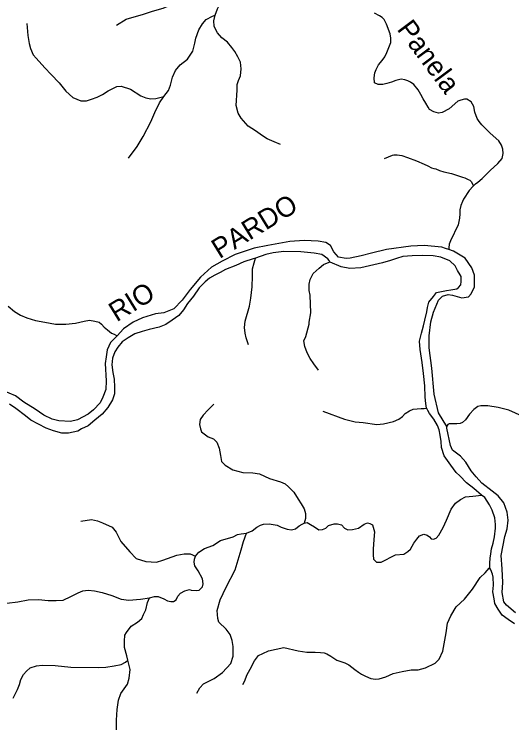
# Model space of a CAD drawing. Extents: x 436.3 to 500.4, y 8231 to 8286.4.
# Drawn here: x 451.75 to 456.78, y 8274.32 to 8281.47 of the extents above; entities that cross this region are included whole.
import ezdxf
from ezdxf.enums import TextEntityAlignment as Align

# ---------------------------------------------------------------- set-up
doc = ezdxf.new("R2010")
doc.units = 0
doc.header["$LTSCALE"] = 0.08
doc.linetypes.add('LONG_DASHED', pattern=[7.5, 6, -1.5])
for name, color, linetype, lineweight in [('2', 7, 'Continuous', 25), ('7', 7, 'Continuous', 25), ('9', 7, 'LONG_DASHED', 25)]:
    doc.layers.add(name, color=color, linetype=linetype, lineweight=lineweight)
doc.layers.add('61', color=7, linetype='Continuous')

msp = doc.modelspace()

# ---------------------------------------------------------------- linework, layer by layer
at = {"layer": '2'}
for points in [[(456.1431, 8279.0995), (456.1124, 8279.1098), (456.0752, 8279.1222), (455.8941, 8279.1388), (455.7603, 8279.1332), (455.5152, 8279.0999), (455.3647, 8279.0611), (455.2589, 8279.0334), (455.1474, 8279.0112), (455.1085, 8279.0068), (455.0304, 8279.0224), (454.9814, 8279.0757), (454.9483, 8279.1393), (454.9025, 8279.1697), (454.8236, 8279.1826), (454.6846, 8279.1901), (454.5396, 8279.1792), (454.3167, 8279.1406), (454.1772, 8279.113), (453.9876, 8279.0465), (453.8538, 8278.98), (453.7478, 8278.9189), (453.6363, 8278.8187), (453.5304, 8278.6964), (453.4509, 8278.5869), (453.3673, 8278.498), (453.2668, 8278.4591), (453.1832, 8278.4482), (453.0494, 8278.4094), (452.9546, 8278.3651), (452.8598, 8278.2984), (452.7944, 8278.2282)], [(456.0416, 8278.5878), (456.0805, 8278.6268), (456.1363, 8278.6435), (456.1808, 8278.6379), (456.2755, 8278.6102), (456.3423, 8278.6214), (456.3702, 8278.6493), (456.4037, 8278.7217), (456.4037, 8278.8385), (456.3761, 8278.9141), (456.3091, 8279.011), (456.1921, 8279.0833), (456.1431, 8279.0995)], [(454.9427, 8278.9736), (454.9344, 8278.986), (454.9229, 8279.0046), (454.8601, 8279.0465), (454.7858, 8279.0618), (454.6508, 8279.0754), (454.4795, 8279.0795), (454.3697, 8279.0658), (454.2954, 8279.0488), (454.1922, 8279.0117)], [(455.9875, 8279.0339), (455.8829, 8279.0377), (455.7726, 8279.0358), (455.6795, 8279.0264), (455.6167, 8279.0093), (455.554, 8278.9865), (455.4759, 8278.9638)], [(455.9204, 8277.4976), (455.9136, 8277.5423), (455.906, 8277.6069), (455.9022, 8277.7211), (455.8888, 8277.8466), (455.8736, 8277.9587), (455.8565, 8278.0896), (455.8489, 8278.1732), (455.8679, 8278.2531), (455.8889, 8278.3272), (455.9022, 8278.3862), (455.9212, 8278.4698), (455.9293, 8278.5128), (455.9426, 8278.566), (455.9901, 8278.623), (456.0205, 8278.6629), (456.0529, 8278.6724), (456.1194, 8278.6858), (456.1632, 8278.6915), (456.2259, 8278.701), (456.2431, 8278.7143), (456.2659, 8278.741), (456.2697, 8278.7771), (456.2678, 8278.8246), (456.2583, 8278.8436), (456.2335, 8278.8853), (456.2081, 8278.9353), (456.1548, 8278.9827), (456.0636, 8279.0207), (455.9875, 8279.0339)], [(454.1922, 8279.0117), (454.1678, 8279.0037), (454.0746, 8278.9731), (453.9947, 8278.9372), (453.8881, 8278.8956), (453.8348, 8278.8672), (453.7796, 8278.8406), (453.7263, 8278.8103), (453.6824, 8278.7731), (453.6234, 8278.7105), (453.5644, 8278.6288), (453.5036, 8278.5548), (453.4636, 8278.4883), (453.416, 8278.4314), (453.3504, 8278.3851), (453.2858, 8278.3414), (453.2191, 8278.3149), (453.1182, 8278.2923), (453.0478, 8278.2715), (452.9735, 8278.2469), (452.905, 8278.2052), (452.846, 8278.1654), (452.8022, 8278.1112), (452.7699, 8278.0657), (452.7471, 8278.0029), (452.7415, 8277.9345), (452.7511, 8277.8564), (452.7645, 8277.7899), (452.7665, 8277.71), (452.7666, 8277.6396), (452.7482, 8277.5793), (452.6989, 8277.5034), (452.6438, 8277.435), (452.5695, 8277.3743), (452.5029, 8277.3174), (452.4344, 8277.289), (452.3963, 8277.2643), (452.303, 8277.2436), (452.2364, 8277.2437), (452.1507, 8277.2667), (452.0763, 8277.2954), (451.9227, 8277.3763), (451.8674, 8277.4182), (451.7701, 8277.4945), (451.7071, 8277.5383)], [(455.4759, 8278.9638), (455.2559, 8278.9149), (455.1436, 8278.9055), (455.0561, 8278.9227), (454.9459, 8278.9704), (454.9427, 8278.9736)], [(455.9957, 8277.6374), (455.9734, 8277.8991), (455.9455, 8278.1053), (455.9455, 8278.2278), (455.9622, 8278.367), (455.9914, 8278.4653), (456.0416, 8278.5878)], [(452.7944, 8278.2282), (452.7768, 8278.2096), (452.7282, 8278.1584), (452.6948, 8278.086), (452.6838, 8278.0135), (452.6726, 8277.9467), (452.6841, 8277.774), (452.6786, 8277.6848), (452.6508, 8277.6069), (452.6229, 8277.5513), (452.5561, 8277.479), (452.5003, 8277.4345), (452.3944, 8277.379), (452.3219, 8277.3624), (452.2047, 8277.3682), (452.1377, 8277.385), (452.0539, 8277.4242), (451.9645, 8277.4856), (451.8528, 8277.5582), (451.769, 8277.6196), (451.6405, 8277.6755)], [(456.123, 8277.3107), (456.0402, 8277.4508), (455.9957, 8277.6374)], [(456.4761, 8276.6191), (456.3979, 8276.6869), (456.3237, 8276.742), (456.2553, 8276.8124), (456.2191, 8276.8486), (456.1632, 8276.9225), (456.0967, 8277.0158), (456.0719, 8277.0995), (456.0662, 8277.1586), (456.0586, 8277.2233), (456.0453, 8277.2784), (456.0301, 8277.3222), (455.992, 8277.3869), (455.9483, 8277.442), (455.9328, 8277.4719), (455.9211, 8277.4933), (455.9204, 8277.4976)], [(456.8177, 8275.4285), (456.7286, 8275.5066), (456.7007, 8275.5401), (456.6839, 8275.6351), (456.6893, 8275.7358), (456.6836, 8275.8755), (456.6747, 8276.0095), (456.7112, 8276.1997), (456.7334, 8276.2779), (456.7446, 8276.3673), (456.7333, 8276.4453), (456.7, 8276.5402), (456.6442, 8276.6127), (456.583, 8276.6573), (456.4771, 8276.7408), (456.4215, 8276.8021), (456.3716, 8276.8633), (456.3156, 8276.9526), (456.2623, 8277.0109), (456.181, 8277.0739), (456.1603, 8277.1208), (456.1258, 8277.296), (456.123, 8277.3107)], [(456.5598, 8275.8854), (456.5598, 8275.9326), (456.5617, 8275.9821), (456.5673, 8276.0241), (456.5749, 8276.0757), (456.592, 8276.1329), (456.6054, 8276.1961), (456.6148, 8276.2856), (456.6146, 8276.3213), (456.6089, 8276.3899), (456.5823, 8276.4661), (456.5556, 8276.5194), (456.5083, 8276.5942), (456.484, 8276.6129), (456.4811, 8276.6147), (456.4761, 8276.6191)], [(456.8075, 8275.3192), (456.7428, 8275.363), (456.6839, 8275.4068), (456.642, 8275.4677), (456.6096, 8275.5231), (456.602, 8275.5727), (456.5905, 8275.6415), (456.5942, 8275.7082), (456.5923, 8275.7895), (456.5864, 8275.8219), (456.5686, 8275.863), (456.5601, 8275.8822), (456.5598, 8275.8854)]]:
    msp.add_lwpolyline(points, dxfattribs=at)
at = {"layer": '7'}
for points in [[(456.3914, 8279.7397), (456.3943, 8279.7418), (456.4146, 8279.7603), (456.4371, 8279.7783), (456.481, 8279.816), (456.5625, 8279.8975), (456.6401, 8279.9674), (456.6827, 8280.0178), (456.6935, 8280.0666), (456.689, 8280.1116), (456.6755, 8280.1521), (456.6486, 8280.1971), (456.5632, 8280.2735), (456.4778, 8280.359), (456.4508, 8280.3905), (456.431, 8280.4217), (456.4078, 8280.4837), (456.3969, 8280.5435), (456.3699, 8280.5886), (456.3249, 8280.6156), (456.3025, 8280.6155), (456.2665, 8280.6065), (456.235, 8280.5975), (456.1481, 8280.5185), (456.0783, 8280.4835), (456.0395, 8280.4757), (455.993, 8280.4875), (455.9504, 8280.5123), (455.9342, 8280.5347), (455.9112, 8280.575), (455.8842, 8280.62), (455.8617, 8280.6651), (455.8347, 8280.7101), (455.7924, 8280.7655), (455.7583, 8280.7867), (455.7321, 8280.8032), (455.7005, 8280.8126), (455.6632, 8280.8193), (455.6098, 8280.8049), (455.5649, 8280.7869), (455.5199, 8280.7734), (455.4794, 8280.7645), (455.4308, 8280.7632), (455.3939, 8280.7826), (455.3894, 8280.8321), (455.3984, 8280.8817), (455.4119, 8280.9177), (455.4344, 8280.9627), (455.4704, 8281.0077), (455.4974, 8281.0437), (455.5199, 8281.0887), (455.5604, 8281.1878), (455.5604, 8281.2328), (455.5514, 8281.2779), (455.5154, 8281.3725), (455.4929, 8281.422), (455.4705, 8281.4401), (455.4435, 8281.4581), (455.394, 8281.4852)], [(456.3914, 8279.7397), (456.3898, 8279.7385), (456.3516, 8279.6927), (456.2931, 8279.6072), (456.2841, 8279.5847), (456.2661, 8279.5442), (456.2571, 8279.4993), (456.2571, 8279.4588), (456.2526, 8279.4138), (456.2391, 8279.3463), (456.162, 8279.1863), (456.1484, 8279.1534), (456.1449, 8279.1147), (456.1431, 8279.0995)]]:
    msp.add_lwpolyline(points, dxfattribs=at)
at = {"layer": '9'}
for p, q in [((455.4938, 8280.019), (455.5747, 8280.0513)), ((452.787, 8278.2296), (452.7944, 8278.2282)), ((456.5518, 8275.8799), (456.5598, 8275.8854))]:
    msp.add_line(p, q, dxfattribs=at)
for points in [[(453.7827, 8281.4656), (453.8084, 8281.5279), (453.8487, 8281.6082), (453.889, 8281.714)], [(452.7874, 8281.3631), (452.8865, 8281.4246), (453.0598, 8281.4738), (453.1526, 8281.5045), (453.2578, 8281.5351), (453.3755, 8281.5843), (453.4572, 8281.61)], [(453.2661, 8280.6426), (453.3137, 8280.7046), (453.332, 8280.7594), (453.3544, 8280.8379), (453.3837, 8280.9073), (453.4313, 8280.962), (453.5045, 8281.0203), (453.5594, 8281.1006), (453.5778, 8281.181), (453.5887, 8281.2321), (453.618, 8281.3161), (453.6547, 8281.3781), (453.6949, 8281.4219), (453.7571, 8281.4546), (453.7827, 8281.4656)], [(454.4455, 8280.1585), (454.3797, 8280.1842), (454.3101, 8280.2172), (454.2626, 8280.2466), (454.1931, 8280.2979), (454.1162, 8280.3456), (454.0467, 8280.4261), (454.0175, 8280.4737), (453.9955, 8280.5541), (454.0064, 8280.7075), (454.0061, 8280.7638), (454.0207, 8280.804), (454.039, 8280.8515), (454.0463, 8280.9245), (454.039, 8280.9903), (454.0134, 8281.0451), (453.9841, 8281.0964), (453.9512, 8281.1366), (453.9072, 8281.1915), (453.8524, 8281.2355), (453.8084, 8281.2868), (453.7865, 8281.3233), (453.7755, 8281.3526), (453.7718, 8281.4074), (453.7827, 8281.4656)], [(451.8831, 8281.38), (451.8905, 8281.2593), (451.9053, 8281.179), (451.92, 8281.1278), (451.9457, 8281.0657), (451.975, 8281.0291), (452.0631, 8280.934), (452.1291, 8280.8645), (452.2097, 8280.7804), (452.2758, 8280.6962), (452.3454, 8280.634), (452.4261, 8280.6011), (452.4847, 8280.601), (452.536, 8280.6156), (452.5909, 8280.6374), (452.6459, 8280.6629), (452.7045, 8280.6994), (452.7923, 8280.7431), (452.8363, 8280.7466), (452.9279, 8280.7173), (453.0341, 8280.6514), (453.0835, 8280.6308), (453.1343, 8280.6209), (453.1856, 8280.6245), (453.2661, 8280.6426)], [(452.9076, 8280.022), (452.9953, 8280.1387), (453.0576, 8280.241), (453.1344, 8280.387), (453.1747, 8280.4819), (453.2222, 8280.5805), (453.2661, 8280.6426)], [(455.5747, 8280.0513), (455.5881, 8280.0536), (455.6217, 8280.0536), (455.6704, 8280.0465), (455.7284, 8280.029), (455.8176, 8279.9942), (455.8953, 8279.9604), (455.932, 8279.9434), (455.9704, 8279.9248), (455.9924, 8279.9161), (456.0122, 8279.9118), (456.0517, 8279.8976), (456.0947, 8279.8845), (456.1702, 8279.8649), (456.233, 8279.8464), (456.2818, 8279.83), (456.3073, 8279.8235), (456.3403, 8279.8063), (456.3577, 8279.7982), (456.375, 8279.7819), (456.3878, 8279.753), (456.3914, 8279.7397)], [(454.1194, 8278.1362), (454.098, 8278.2056), (454.0874, 8278.2536), (454.0819, 8278.3123), (454.0873, 8278.3764), (454.1299, 8278.5256), (454.1459, 8278.6056), (454.1565, 8278.723), (454.1618, 8278.8297), (454.1617, 8278.9044), (454.1777, 8278.963), (454.1922, 8279.0117)], [(454.8294, 8277.8789), (454.7814, 8277.943), (454.744, 8277.9965), (454.712, 8278.0553), (454.6906, 8278.1193), (454.6799, 8278.178), (454.7013, 8278.2206), (454.7332, 8278.3433), (454.7332, 8278.3646), (454.7492, 8278.4606), (454.7438, 8278.6366), (454.7331, 8278.6847), (454.7331, 8278.7487), (454.7438, 8278.7967), (454.7758, 8278.8553), (454.8345, 8278.9086), (454.8772, 8278.9459), (454.9347, 8278.9697), (454.9427, 8278.9736)], [(451.6924, 8278.5264), (451.7581, 8278.4734), (451.8175, 8278.4359), (451.8831, 8278.4078), (451.9707, 8278.3828), (452.0643, 8278.364), (452.1723, 8278.3435), (452.2753, 8278.3434), (452.3721, 8278.3556), (452.4626, 8278.3742), (452.5157, 8278.3835), (452.5687, 8278.374), (452.6125, 8278.3646), (452.6375, 8278.3459), (452.6625, 8278.3146), (452.6969, 8278.2865), (452.7375, 8278.2553), (452.7625, 8278.2428), (452.787, 8278.2296)], [(453.7714, 8277.5381), (453.7144, 8277.4811), (453.6626, 8277.4242), (453.6316, 8277.3828), (453.6264, 8277.331), (453.6368, 8277.2894), (453.6472, 8277.2584), (453.6731, 8277.2375), (453.7146, 8277.2064), (453.7665, 8277.1854), (453.8028, 8277.1543), (453.8236, 8277.092), (453.8392, 8277.0194), (453.8497, 8276.9571), (453.886, 8276.9207), (453.9638, 8276.8739), (454.0623, 8276.8478), (454.1659, 8276.8424), (454.2333, 8276.8318), (454.3318, 8276.785), (454.4459, 8276.7536), (454.4924, 8276.7328), (454.5236, 8276.7016), (454.5806, 8276.6496), (454.6221, 8276.5769), (454.6532, 8276.5302), (454.684, 8276.4815), (454.6964, 8276.432), (454.6952, 8276.3836), (454.6821, 8276.3342)], [(456.9774, 8277.3732), (456.7517, 8277.4769), (456.6417, 8277.5034), (456.5392, 8277.5187), (456.4679, 8277.5186), (456.4382, 8277.5127), (456.3966, 8277.4829), (456.3521, 8277.4352), (456.3134, 8277.3787), (456.2838, 8277.3519), (456.26, 8277.3429), (456.2244, 8277.34), (456.1917, 8277.34), (456.165, 8277.34), (456.1482, 8277.338), (456.1359, 8277.33), (456.1248, 8277.3157), (456.123, 8277.3107)], [(454.8722, 8277.4652), (455.091, 8277.3849), (455.1977, 8277.3582), (455.2777, 8277.3528), (455.4164, 8277.3314), (455.4858, 8277.3367), (455.5871, 8277.3634), (455.6404, 8277.3848), (455.6777, 8277.4115), (455.7044, 8277.4435), (455.747, 8277.4702), (455.7844, 8277.4863), (455.8644, 8277.4916), (455.897, 8277.4945), (455.9204, 8277.4976)], [(454.6821, 8276.3342), (454.7147, 8276.3423), (454.7473, 8276.3219), (454.788, 8276.2973), (454.8328, 8276.2686), (454.8694, 8276.2727), (454.9019, 8276.2849), (454.9305, 8276.3134), (454.9874, 8276.3297), (455.02, 8276.3297), (455.0607, 8276.3174), (455.0912, 8276.2848), (455.1238, 8276.2685), (455.1726, 8276.2724), (455.2337, 8276.2847), (455.2907, 8276.3255), (455.3232, 8276.3377), (455.3476, 8276.3336), (455.3721, 8276.3173), (455.3925, 8276.2479), (455.3884, 8276.1704), (455.3803, 8276.0724), (455.3804, 8276.0152), (455.3845, 8275.9703), (455.413, 8275.9417), (455.4619, 8275.9416), (455.6043, 8276.0152), (455.6897, 8276.0233), (455.7303, 8276.0479), (455.7588, 8276.0724), (455.7913, 8276.1337), (455.8198, 8276.1745), (455.8483, 8276.2071), (455.893, 8276.2235), (455.9255, 8276.2154), (455.95, 8276.199), (455.9663, 8276.1786), (455.9907, 8276.1746), (456.0151, 8276.1827), (456.0435, 8276.2155), (456.0882, 8276.293), (456.1207, 8276.3665), (456.1695, 8276.4767), (456.2113, 8276.5383), (456.2641, 8276.5751), (456.3129, 8276.5996), (456.3862, 8276.6079), (456.4761, 8276.6191)], [(452.4262, 8276.3545), (452.5366, 8276.3726), (452.5964, 8276.3586), (452.6471, 8276.34), (452.7437, 8276.2938), (452.7852, 8276.243), (452.8312, 8276.1508), (452.9233, 8276.0446), (452.9878, 8275.9799), (453.0844, 8275.9474), (453.1902, 8275.9425), (453.2545, 8275.9608), (453.3971, 8276.011), (453.4706, 8276.0247), (453.5304, 8276.0245), (453.5869, 8276.0017)], [(454.1023, 8276.2336), (454.157, 8276.2575), (454.2058, 8276.2942), (454.2423, 8276.3144), (454.2709, 8276.3266), (454.331, 8276.3287), (454.4093, 8276.3141), (454.4501, 8276.2937), (454.5112, 8276.2732), (454.5559, 8276.269), (454.5967, 8276.2772), (454.6333, 8276.3097), (454.6618, 8276.326), (454.6821, 8276.3342)], [(453.5869, 8276.0017), (453.6194, 8276.0424), (453.6765, 8276.079), (453.762, 8276.1114), (453.8393, 8276.1602), (453.9655, 8276.1967), (454.0104, 8276.2211), (454.0484, 8276.2292), (454.1023, 8276.2336)], [(453.5997, 8274.6175), (453.6299, 8274.6719), (453.6661, 8274.7142), (453.7746, 8274.7684), (453.859, 8274.8286), (453.9434, 8274.9193), (453.9675, 8274.9918), (453.9674, 8275.0886), (453.9554, 8275.1492), (453.9372, 8275.2098), (453.8949, 8275.2643), (453.8225, 8275.3372), (453.8104, 8275.3735), (453.8044, 8275.4522), (453.8345, 8275.561), (453.8947, 8275.6879), (453.9861, 8275.8657), (454.0463, 8276.0651), (454.0703, 8276.1496), (454.1023, 8276.2336)], [(453.1196, 8275.5821), (453.1701, 8275.5954), (453.2078, 8275.5952), (453.2644, 8275.5714), (453.3021, 8275.5524), (453.335, 8275.5429), (453.3633, 8275.5428), (453.3916, 8275.5616), (453.4056, 8275.5994), (453.4339, 8275.6276), (453.4763, 8275.651), (453.5234, 8275.6652), (453.5422, 8275.6603), (453.594, 8275.6554), (453.6222, 8275.6601), (453.6552, 8275.6931), (453.6646, 8275.7214), (453.6551, 8275.7733), (453.6127, 8275.8537), (453.5797, 8275.9057), (453.5706, 8275.9405), (453.5747, 8275.9731), (453.5869, 8276.0017)], [(454.0628, 8274.7051), (454.0842, 8274.7425), (454.1055, 8274.8014), (454.1375, 8274.8603), (454.1801, 8274.9459), (454.2227, 8274.9994), (454.2655, 8275.0207), (454.3241, 8275.0474), (454.4789, 8275.0793), (454.623, 8275.0469), (454.7088, 8275.0313), (454.7941, 8275.0312), (454.8475, 8275.0311), (454.8849, 8275.0258), (454.9115, 8275.015), (454.9542, 8274.9935), (455.013, 8274.9506), (455.093, 8274.9236), (455.1333, 8274.9044), (455.1944, 8274.8592), (455.2318, 8274.8325), (455.2639, 8274.8109), (455.3014, 8274.7901), (455.3557, 8274.7678), (455.4027, 8274.759), (455.4399, 8274.7626), (455.5092, 8274.7841), (455.5839, 8274.8162), (455.6745, 8274.8376), (455.7651, 8274.8537), (455.8345, 8274.8537), (455.9091, 8274.8751), (456.005, 8274.9234), (456.0478, 8274.9609), (456.0851, 8275.0413), (456.1168, 8275.2289), (456.1327, 8275.3254), (456.1646, 8275.4004), (456.2179, 8275.4916), (456.3031, 8275.5666), (456.3829, 8275.6685), (456.4628, 8275.7863), (456.5108, 8275.8346), (456.5518, 8275.8799)], [(451.6799, 8275.5262), (451.792, 8275.5414), (451.8963, 8275.5605), (452.0007, 8275.564), (452.0973, 8275.556), (452.1798, 8275.5552), (452.2493, 8275.5588), (452.3265, 8275.5935), (452.3999, 8275.6319), (452.4462, 8275.6511), (452.5003, 8275.6586), (452.566, 8275.6507), (452.6432, 8275.635), (452.7415, 8275.6039), (452.8342, 8275.5688), (452.9115, 8275.5569), (453.0311, 8275.5682), (453.1196, 8275.5821)], [(452.9031, 8274.9515), (452.8925, 8274.9964), (452.8689, 8275.0815), (452.8688, 8275.1429), (452.8735, 8275.2043), (452.8876, 8275.2326), (452.9348, 8275.2939), (453.0007, 8275.3361), (453.043, 8275.3738), (453.0619, 8275.4115), (453.0854, 8275.4587), (453.0996, 8275.5342), (453.1196, 8275.5821)], [(451.7425, 8274.5669), (451.7657, 8274.6093), (451.7889, 8274.6557), (451.8082, 8274.706), (451.8198, 8274.7563), (451.8469, 8274.8065), (451.8778, 8274.8413), (451.9164, 8274.876), (451.9783, 8274.8952), (452.0362, 8274.9027), (452.1676, 8274.8983), (452.326, 8274.8824), (452.6096, 8274.8789), (452.6791, 8274.8825), (452.7641, 8274.8938), (452.8336, 8274.9091), (452.8799, 8274.9322), (452.9031, 8274.9515)], [(452.7042, 8273.584), (452.6806, 8273.6503), (452.6806, 8273.6975), (452.69, 8273.7448), (452.7654, 8273.9147), (452.7937, 8273.9855), (452.789, 8274.1715), (452.789, 8274.3463), (452.7937, 8274.4551), (452.8078, 8274.5496), (452.8314, 8274.6157), (452.8973, 8274.7099), (452.9162, 8274.7712), (452.9256, 8274.8562), (452.9031, 8274.9515)]]:
    msp.add_lwpolyline(points, dxfattribs=at)

# ---------------------------------------------------------------- texts
at = {"layer": '61'}
for s, rotation, p in [('Córrego                                Panela', 306.719, (454.8629, 8282.3294)), ('RIO          PARDO', 31.599, (453.7133, 8278.9305))]:
    msp.add_text(s, height=0.2, rotation=rotation, dxfattribs=at).set_placement(p, align=Align.CENTER)

doc.saveas('drawing.dxf')
